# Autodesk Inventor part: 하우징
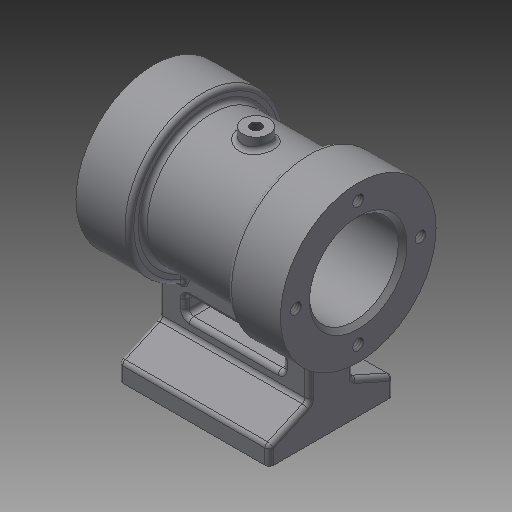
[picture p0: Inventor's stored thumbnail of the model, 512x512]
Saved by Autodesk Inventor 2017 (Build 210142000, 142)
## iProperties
Created: 2018-01
Part Number: 하우징
Material: 일반
Document SubType Name: Modeling
Designer: mduedu
Density: 1 g/cm^3
Mass: 31.9228 g
Surface Area: 128.667 cm^2
Volume: 31.9228 cm^3
Appearance: 기본값
Author: mduedu
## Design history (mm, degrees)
sketch "스케치1"
  geometry: L1 (-23, 0)-(23, 0); L2 (-23, 0)-(-23, 17.5); L3 (-23, 17.5)-(-11, 17.5); L4 (-11, 17.5)-(-11, 14.5); L5 (-11, 14.5)-(11, 14.5); L6 (11, 14.5)-(11, 17.5); L7 (11, 17.5)-(23, 17.5); L8 (23, 17.5)-(23, 0); 2 further points
  constraints: 16 end point, 3 parallel, 2 collinear, 2 perpendicular, 1 coincident, 1 horizontal, 1 midpoint, 1 vertical
  dimensions: "d0" = 46 distance of L1.start L1.end; "d2" = 12 distance of L2.end L3.end; "d3" = 12 distance of L6.end L7.end (= d2); "d4" = 35 diameter of L3 L1; "d5" = 29 diameter of L5 L1
revolve "회전1" sketch "스케치1" stored, may be unused: angle "d6" = 90 deg
hole "구멍1" diameter "d9" = 20; stored, may be unused: countersink angle "d13" = 90 deg, drill point angle "d15" = 118 deg; dims "d7" = 10, "d8" = 10, "d10" = 6, "d11" = 4, "d12" = 2, "d14" = 8
fillet "모깎기1" dims "d16" = 1
sketch "스케치2"
  geometry: L1 (0, 0)-(-34, 0); L2 (-34, 14)-(-34, -14); L3 (-34, 14)-(-30, 14); L4 (-30, 14)-(-26, 5); L5 (-26, 5)-(-13.611, 5); L6 (-26, -5)-(-13.611, -5); L7 (-30, -14)-(-26, -5); L8 (-34, -14)-(-30, -14); C1 r 10 at (0, 0) reference; A1 r 14.5 centre (0, 0) between (-13.611, 5) and (-13.611, -5); 2 further points
  constraints: 16 end point, 3 symmetric about line, 2 perpendicular, 2 point on circle, 1 centre point, 1 coincident, 1 horizontal, 1 midpoint, 1 parallel, 2 other
  dimensions: "d17" = 34 distance of L1.end L1.start; "d18" = 28 distance between parallel lines of L8 L3; "d19" = 10 distance between parallel lines of L6 L5; "d20" = 4 distance of L2.end L7.start; "d21" = 8 distance from line of L6.start L2
extrude "돌출1" join sketch "스케치2" stored distance "d22" = 34; taper "d23" = 0 deg
sketch "스케치3"
  geometry: L1 (-11, -19)-(11, -19); L2 (11, -19)-(11, -23); L3 (11, -23)-(-11, -23); L4 (-11, -23)-(-11, -19); L5 (-17, -16.771)-(-17, -26) reference; L6 (17, -26)-(17, -16.771) reference; L7 (-17, -34)-(17, -34) reference; 1 further point
  constraints: 8 end point, 2 parallel, 1 horizontal, 1 perpendicular
  dimensions: "d24" = 6 distance between parallel lines of L4 L5; "d25" = 6 distance between parallel lines of L2 L6; "d26" = 11 distance between parallel lines of L3 L7; "d27" = 4 distance of L1.end L2.end
extrude "돌출2" cut sketch "스케치3" stored distance "d28" = 34; taper "d29" = 0 deg
fillet "모깎기2" dims "d30" = 1
fillet "모깎기3" dims "d31" = 1
fillet "모깎기4" dims "d32" = 1
fillet "모깎기5" dims "d33" = 1
fillet "모깎기6" dims "d34" = 1
sketch "스케치4" dims "d7" = 10, "d8" = 10
  geometry: C1 r 17.5 at (0, 0) reference; A1 r 14 centre (0, 0) between (0, 14) and (-14, 0); 2 further points
  constraints: 4 point on circle, 2 horizontal alignment, 2 vertical alignment, 1 centre point, 1 coincident
  dimensions: "d75" = 28 diameter of A1
hole "구멍2" sketch "스케치4" at (-14, 0), (0, -14), (14, 0), (0, 14) diameter "d35" = 2.459; stored, may be unused: countersink angle "d39" = 90 deg, drill point angle "d41" = 120 deg; dims "d36" = 5.5, "d37" = 4, "d38" = 2, "d40" = 7
sketch "스케치5"
  geometry: A1 r 17.5 centre (0, 0) between (5.676, -16.554) and (-5.676, -16.554) reference; A2 r 14 centre (0, 0) between (0, 14) and (14, 0); 2 further points
  constraints: 4 point on circle, 2 horizontal alignment, 2 vertical alignment, 1 centre point, 1 coincident
  dimensions: "d80" = 28 diameter of A2
hole "구멍4" sketch "스케치5" at (-14, 0), (0, -14), (14, 0), (0, 14) diameter "d42" = 2.459; stored, may be unused: countersink angle "d46" = 90 deg, drill point angle "d48" = 120 deg; dims "d43" = 5.5, "d44" = 4, "d45" = 2, "d47" = 7
sketch "스케치6"
  geometry: 2 further points
  constraints: 2 other
hole "구멍5" sketch "스케치6" at (7, 14), (25, 14) diameter "d49" = 2.459; stored, may be unused: countersink angle "d53" = 90 deg, drill point angle "d55" = 120 deg; dims "d50" = 6, "d51" = 4, "d52" = 2, "d54" = 8
node "작업 평면1"
sketch "스케치7"
  geometry: L1 (-23, 17.5)-(-23, -17.5) reference; C1 r 3 at (0, 0); 1 further point
  constraints: 2 coincident, 1 centre point
  dimensions: "d57" = 6 diameter of C1
extrude "돌출3" join sketch "스케치7" stored distance "d61" = 10; taper "d62" = 0 deg
fillet "모깎기7" dims "d63" = 1
hole "구멍6" diameter "d66" = 2.459; stored, may be unused: countersink angle "d70" = 90 deg, drill point angle "d72" = 118 deg; dims "d64" = 10, "d65" = 10, "d67" = 6, "d68" = 4, "d69" = 2, "d71" = 8
chamfer "모따기1" distance "d77" = 1; stored, may be unused: second distance "d78" = 2, angle "d79" = 45 deg
node "솔리드1"
node "절단 모서리 투영1"
other parameters: "d56" = 17
